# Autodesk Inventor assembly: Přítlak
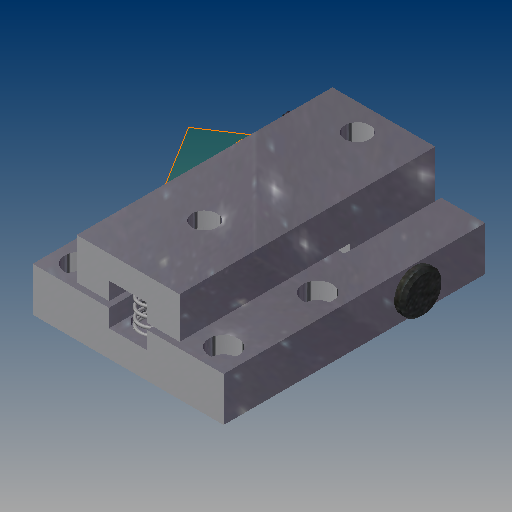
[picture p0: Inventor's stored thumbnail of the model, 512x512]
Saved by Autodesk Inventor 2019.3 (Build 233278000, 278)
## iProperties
Created: 2019-01
Part Number: Přítlak
Material: Všeobecné
Document SubType Name: Assembly
Designer: B-hon
Stock Number: 19-A3-S-07
Mass: 340.479 g
Surface Area: 356.664 cm^2
Volume: 117.016 cm^3
Density: 2.90967 g/cm^3
Author: B-hon
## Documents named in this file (7)
- C:\Users\B-hon\OneDrive\Plocha\Bakalářka22\Přítlak spodní\Levý\Přítlak3s.iam
- C:\Users\B-hon\OneDrive\Plocha\Bakalářka22\Přítlak spodní\Levý\Příruba vozíku3s.ipt
- C:\Users\B-hon\OneDrive\Plocha\Bakalářka22\Přítlak spodní\Levý\Příruba desky3s.ipt
- C:\Users\B-hon\OneDrive\Documents\Inventor\Content Center Files\R2019\cs-CZ\BS EN 22 341  B\ISO 2341 - B - 8 x 70BS EN.ipt
- C:\Users\B-hon\OneDrive\Documents\Inventor\Content Center Files\R2019\cs-CZ\CSN EN ISO 2338\ISO 2338 - 6 h8 x 20CSN EN.ipt
- C:\Users\B-hon\OneDrive\Documents\Inventor\Content Center Files\R2019\cs-CZ\CSN EN ISO 1234\CSN EN ISO 1234 - 2x14 x 8 - 7.ipt
- C:\Users\B-hon\OneDrive\Plocha\Bakalářka22\Přítlak spodní\Levý\Přítlak3s\Design Accelerator\Tlačná pružina3.iam
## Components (6 placed, 6 different names)
1. Příruba vozíku3s:1 — Vložit:1, Úhel:1, Vložit:4, Úhel:2, Úhel:3, Proti sobě:6
2. Příruba desky3s:1 — Vložit:1, Úhel:1, Vložit:3, Proti sobě:5, Úhel:4
3. BS EN 22341 B B - 8 x 70:1 — Vložit:4, Proti sobě:1
4. CSN EN ISO 2338 6 h8 x 20:1 — Vložit:3
5. CSN EN ISO 1234 2x14:1 — Proti sobě:1, Proti sobě:2, Proti sobě:3, Proti sobě:4, Úhel:4
6. Tlačná pružina:1 [sub-assembly] — Proti sobě:5, Proti sobě:6
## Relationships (13: Mate 6, Angle 4, Insert 3)
- Vložit:1 [Insert]: Příruba vozíku3s:1 ↔ Příruba desky3s:1
- Úhel:1 [Angle]: Příruba vozíku3s:1 ↔ Příruba desky3s:1
- Vložit:3 [Insert]: Příruba desky3s:1 ↔ CSN EN ISO 2338 6 h8 x 20:1
- Vložit:4 [Insert]: Příruba vozíku3s:1 ↔ BS EN 22341 B B - 8 x 70:1
- Úhel:2 [Angle]: Příruba vozíku3s:1
- Proti sobě:1 [Mate]: BS EN 22341 B B - 8 x 70:1 ↔ CSN EN ISO 1234 2x14:1
- Proti sobě:2 [Mate]: CSN EN ISO 1234 2x14:1
- Proti sobě:3 [Mate]: CSN EN ISO 1234 2x14:1
- Proti sobě:4 [Mate]: CSN EN ISO 1234 2x14:1
- Úhel:3 [Angle]: Příruba vozíku3s:1
- Proti sobě:5 [Mate]: Příruba desky3s:1 ↔ Tlačná pružina:1
- Proti sobě:6 [Mate]: Příruba vozíku3s:1 ↔ Tlačná pružina:1
- Úhel:4 [Angle]: Příruba desky3s:1 ↔ CSN EN ISO 1234 2x14:1
